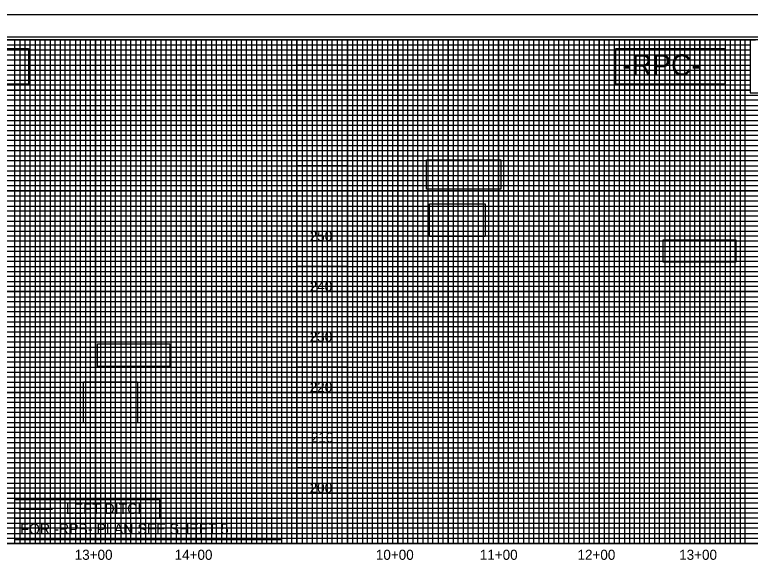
# Model space of a CAD drawing. Extents: x 1810963 to 1812960, y 722070 to 723170.
# Drawn here: x 1811500 to 1812230, y 722624 to 723170 of the extents above; entities that cross this region are included whole.
import ezdxf

# ---------------------------------------------------------------- set-up
doc = ezdxf.new("R2010")
doc.units = 0
for name, color, linetype in [('Exist Horizontal Alignment Tick Label', 7, 'Continuous'), ('Old_Level_11', 7, 'Continuous'), ('Old_Level_2', 7, 'Continuous'), ('Prop Conc 2ft 6in Curb and Gutter', 7, 'Continuous'), ('Prop RDY Traffic Signal CELL', 7, 'Continuous'), ('Prop Shade Heavy', 7, 'Continuous'), ('Prop Shade Light', 7, 'Continuous'), ('Prop Vertical Profile Ditch Grade Left', 7, 'Continuous'), ('Scratch_Level_3', 7, 'Continuous'), ('Sheet Block Title CELL', 7, 'Continuous'), ('Sheet Layout Profile Border Port 1', 7, 'Continuous'), ('Sheet North Arrow CELL', 7, 'Continuous'), ('Sheet Symbology CELL', 7, 'Continuous'), ('Sheet Title CELL', 7, 'Continuous')]:
    doc.layers.add(name, color=color, linetype=linetype)

msp = doc.modelspace()

# ---------------------------------------------------------------- linework, layer by layer
at = {"layer": 'Old_Level_11'}
msp.add_lwpolyline([(1810976.46, 722092.33), (1812642.96, 722092.33), (1812642.96, 723147.43), (1810976.46, 723147.43)], close=True, dxfattribs=at)
at = {"layer": 'Old_Level_2'}
for p, q in [((1811830.46, 723119.88), (1811780.46, 723119.88)), ((1811830.46, 723094.88), (1811780.46, 723094.88)), ((1811830.46, 723069.88), (1811780.46, 723069.88)), ((1811830.46, 723044.88), (1811780.46, 723044.88)), ((1811830.46, 723019.88), (1811780.46, 723019.88)), ((1811830.46, 722994.88), (1811780.46, 722994.88)), ((1811830.46, 722969.88), (1811780.46, 722969.88)), ((1811830.46, 722944.88), (1811780.46, 722944.88)), ((1811830.46, 722919.88), (1811780.46, 722919.88)), ((1811830.46, 722894.88), (1811780.46, 722894.88)), ((1811830.46, 722869.88), (1811780.46, 722869.88)), ((1811830.46, 722844.88), (1811780.46, 722844.88)), ((1811830.46, 722819.88), (1811780.46, 722819.88)), ((1811830.46, 722794.88), (1811780.46, 722794.88)), ((1811830.46, 722769.88), (1811780.46, 722769.88)), ((1811830.46, 722744.88), (1811780.46, 722744.88)), ((1811830.46, 722719.88), (1811780.46, 722719.88)), ((1811830.46, 722694.88), (1811780.46, 722694.88)), ((1811830.46, 722669.88), (1811780.46, 722669.88))]:
    msp.add_line(p, q, dxfattribs=at)
for points in [[(1811780.46, 723144.88), (1811830.46, 723144.88), (1811830.46, 722644.88), (1811780.46, 722644.88)], [(1811405.74, 723136.45), (1811513.83, 723136.45), (1811513.83, 723101.06), (1811405.74, 723101.06)], [(1812096.99, 723136.45), (1812205.08, 723136.45), (1812205.08, 723101.06), (1812096.99, 723101.06)], [(1811909.02, 723025.89), (1811982.71, 723025.89), (1811982.71, 722996.59), (1811909.02, 722996.59)], [(1811911.85, 722982.22), (1811967.42, 722982.22), (1811967.42, 722949.63), (1811911.85, 722949.63)], [(1812144.06, 722946.5), (1812215.98, 722946.5), (1812215.98, 722924.17), (1812144.06, 722924.17)], [(1811582.43, 722843.13), (1811654.35, 722843.13), (1811654.35, 722820.5), (1811582.43, 722820.5)], [(1811568.44, 722805.35), (1811622.21, 722805.35), (1811622.21, 722764.67), (1811568.44, 722764.67)], [(1811500.38, 722688.37), (1811644.05, 722688.37), (1811644.05, 722669.88), (1811500.38, 722669.88)], [(1811500.38, 722669.88), (1811765.06, 722669.88), (1811765.06, 722648.36), (1811500.38, 722648.36)]]:
    msp.add_lwpolyline(points, close=True, dxfattribs=at)
at = {"layer": 'Prop Conc 2ft 6in Curb and Gutter'}
for p, q in [((1811530.46, 722644.88), (1811530.46, 723144.88)), ((1811580.46, 722644.88), (1811580.46, 723144.88)), ((1811630.46, 722644.88), (1811630.46, 723144.88)), ((1811680.46, 722644.88), (1811680.46, 723144.88)), ((1811730.46, 722644.88), (1811730.46, 723144.88)), ((1811780.46, 722644.88), (1811780.46, 723144.88)), ((1811780.46, 722644.88), (1811780.46, 723144.88)), ((1811780.46, 723144.88), (1811780.46, 722644.88)), ((1811830.46, 722644.88), (1811830.46, 723144.88)), ((1811830.46, 722644.88), (1811830.46, 723144.88)), ((1811830.46, 723144.88), (1811830.46, 722644.88)), ((1811880.46, 722644.88), (1811880.46, 723144.88)), ((1811880.46, 723144.88), (1811880.46, 722644.88)), ((1811880.46, 723144.88), (1811880.46, 722644.88)), ((1811930.46, 722644.88), (1811930.46, 723144.88)), ((1811930.46, 723144.88), (1811930.46, 722644.88)), ((1811930.46, 723144.88), (1811930.46, 722644.88)), ((1811980.46, 722644.88), (1811980.46, 723144.88)), ((1812030.46, 722644.88), (1812030.46, 723144.88)), ((1812080.46, 722644.88), (1812080.46, 723144.88)), ((1812130.46, 722644.88), (1812130.46, 723144.88)), ((1812180.46, 722644.88), (1812180.46, 723144.88)), ((1812230.42, 723094.88), (1811130.46, 723094.88)), ((1812430.41, 723044.88), (1811130.46, 723044.88)), ((1812430.46, 722994.88), (1811130.46, 722994.88)), ((1812630.46, 722944.88), (1811130.46, 722944.88)), ((1812630.46, 722894.88), (1811130.46, 722894.88)), ((1812630.46, 722844.88), (1811130.46, 722844.88)), ((1812630.46, 722794.88), (1811130.46, 722794.88)), ((1812630.46, 722744.88), (1811130.46, 722744.88)), ((1812630.46, 722694.88), (1811130.46, 722694.88))]:
    msp.add_line(p, q, dxfattribs=at)
at = {"layer": 'Prop RDY Traffic Signal CELL'}
msp.add_line((1812647.46, 723169.88), (1810963.46, 723169.88), dxfattribs=at)
at = {"layer": 'Prop Shade Heavy'}
for p, q in [((1811780.46, 723144.88), (1811830.46, 723144.88)), ((1811880.46, 723144.88), (1811930.46, 723144.88))]:
    msp.add_line(p, q, dxfattribs=at)
for points in [[(1811480.46, 722644.88), (1811530.46, 722644.88), (1811530.46, 723144.88), (1811580.46, 723144.88), (1811580.46, 722644.88), (1811630.46, 722644.88), (1811630.46, 723144.88), (1811680.46, 723144.88), (1811680.46, 722644.88), (1811730.46, 722644.88), (1811730.46, 723144.88), (1811780.46, 723144.88), (1811780.46, 722644.88), (1811830.46, 722644.88), (1811830.46, 723144.88), (1811880.46, 723144.88), (1811880.46, 722644.88), (1811930.46, 722644.88), (1811930.46, 723144.88), (1811980.46, 723144.88), (1811980.46, 722644.88), (1812030.46, 722644.88), (1812030.46, 723144.88), (1812080.46, 723144.88), (1812080.46, 722644.88), (1812130.46, 722644.88), (1812130.46, 723144.88), (1812180.46, 723144.88), (1812180.46, 722644.88), (1812230.46, 722644.88)], [(1811130.46, 723094.88), (1812230.42, 723094.88)], [(1812430.46, 723044.88), (1811130.46, 723044.88), (1811130.46, 722994.88), (1812430.46, 722994.88)], [(1812630.46, 722944.88), (1811130.46, 722944.88), (1811130.46, 722894.88), (1812630.46, 722894.88)], [(1812630.46, 722844.88), (1811130.46, 722844.88), (1811130.46, 722794.88), (1812630.46, 722794.88)], [(1812630.46, 722744.88), (1811130.46, 722744.88), (1811130.46, 722744.88), (1811130.46, 722694.88), (1812630.46, 722694.88)]]:
    msp.add_lwpolyline(points, dxfattribs=at)
at = {"layer": 'Prop Shade Light'}
for p, q in [((1811455.46, 723144.88), (1811505.46, 723144.88)), ((1811505.46, 723144.88), (1811505.46, 722644.88)), ((1811555.46, 722644.88), (1811555.46, 723144.88)), ((1811555.46, 723144.88), (1811605.46, 723144.88)), ((1811605.46, 723144.88), (1811605.46, 722644.88)), ((1811655.46, 722644.88), (1811655.46, 723144.88)), ((1811655.46, 723144.88), (1811705.46, 723144.88)), ((1811705.46, 723144.88), (1811705.46, 722644.88)), ((1811755.46, 722644.88), (1811755.46, 723144.88)), ((1811755.46, 723144.88), (1811805.46, 723144.88)), ((1811805.46, 723144.88), (1811805.46, 722644.88)), ((1811855.46, 722644.88), (1811855.46, 723144.88)), ((1811855.46, 723144.88), (1811905.46, 723144.88)), ((1811905.46, 723144.88), (1811905.46, 722644.88)), ((1811955.46, 722644.88), (1811955.46, 723144.88)), ((1811955.46, 723144.88), (1812005.46, 723144.88)), ((1812005.46, 723144.88), (1812005.46, 722644.88)), ((1812055.46, 722644.88), (1812055.46, 723144.88)), ((1812055.46, 723144.88), (1812105.46, 723144.88)), ((1812105.46, 723144.88), (1812105.46, 722644.88)), ((1812155.46, 722644.88), (1812155.46, 723144.88)), ((1812155.46, 723144.88), (1812205.46, 723144.88)), ((1812205.46, 723144.88), (1812205.46, 722644.88)), ((1811130.46, 723119.88), (1812230.42, 723119.88)), ((1811505.46, 722644.88), (1811555.46, 722644.88)), ((1811605.46, 722644.88), (1811655.46, 722644.88)), ((1811705.46, 722644.88), (1811755.46, 722644.88)), ((1811755.46, 722644.88), (1811755.46, 722644.88)), ((1811805.46, 722644.88), (1811855.46, 722644.88)), ((1811905.46, 722644.88), (1811955.46, 722644.88)), ((1812005.46, 722644.88), (1812055.46, 722644.88)), ((1812105.46, 722644.88), (1812155.46, 722644.88)), ((1812205.46, 722644.88), (1812255.46, 722644.88))]:
    msp.add_line(p, q, dxfattribs=at)
for points in [[(1812430.46, 723069.88), (1811130.46, 723069.88), (1811130.46, 723019.88), (1812430.46, 723019.88)], [(1812630.46, 722969.88), (1811130.46, 722969.88), (1811130.46, 722919.88), (1812455.46, 722919.88)], [(1812630.46, 722869.88), (1811130.46, 722869.88), (1811130.46, 722819.88), (1812630.46, 722819.88)], [(1812630.46, 722769.88), (1811130.46, 722769.88), (1811130.46, 722719.88), (1812630.46, 722719.88)], [(1812630.46, 722669.88), (1811130.46, 722669.88)]]:
    msp.add_lwpolyline(points, dxfattribs=at)
at = {"layer": 'Prop Vertical Profile Ditch Grade Left'}
msp.add_line((1811504.29, 722679.06), (1811537.94, 722679.06), dxfattribs=at)
at = {"layer": 'Scratch_Level_3'}
msp.add_lwpolyline([(1811180.46, 723144.88), (1812230.46, 723144.88), (1812230.46, 723092.45), (1812430.5, 723092.45), (1812430.41, 722983.83), (1812580.46, 722983.83), (1812580.46, 722644.88), (1811180.46, 722644.88)], close=True, dxfattribs=at)
at = {"layer": 'Sheet Layout Profile Border Port 1'}
msp.add_lwpolyline([(1811180.46, 722983.83), (1811180.46, 722644.88), (1812580.46, 722644.88), (1812580.46, 722983.83)], dxfattribs=at)
at = {"layer": 'Sheet North Arrow CELL'}
msp.add_lwpolyline([(1810963.46, 722069.88), (1812647.46, 722069.88), (1812647.46, 723169.88), (1810963.46, 723169.88)], close=True, dxfattribs=at)
at = {"layer": 'Sheet Symbology CELL'}
msp.add_line((1811130.46, 722644.88), (1812630.46, 722644.88), dxfattribs=at)
msp.add_lwpolyline([(1812630.46, 723144.88), (1811130.46, 723144.88), (1811130.46, 722094.88), (1812630.46, 722094.88)], close=True, dxfattribs=at)
at = {"layer": 'Sheet Title CELL'}
for p, q in [((1811180.46, 723139.88), (1812230.42, 723139.88)), ((1812015.46, 722644.88), (1812015.46, 723144.88)), ((1812015.46, 723144.88), (1812020.46, 723144.88)), ((1812020.46, 723144.88), (1812020.46, 722644.88)), ((1812025.46, 722644.88), (1812025.46, 723144.88)), ((1812025.46, 723144.88), (1812035.46, 723144.88)), ((1812035.46, 723144.88), (1812035.46, 722644.88)), ((1812040.46, 722644.88), (1812040.46, 723144.88)), ((1812040.46, 723144.88), (1812045.46, 723144.88)), ((1812045.46, 723144.88), (1812045.46, 722644.88)), ((1812050.46, 722644.88), (1812050.46, 723144.88)), ((1812050.46, 723144.88), (1812060.46, 723144.88)), ((1812060.46, 723144.88), (1812060.46, 722644.88)), ((1812065.46, 722644.88), (1812065.46, 723144.88)), ((1812065.46, 723144.88), (1812070.46, 723144.88)), ((1812070.46, 723144.88), (1812070.46, 722644.88)), ((1812075.46, 722644.88), (1812075.46, 723144.88)), ((1812075.46, 723144.88), (1812085.46, 723144.88)), ((1812085.46, 723144.88), (1812085.46, 722644.88)), ((1812090.46, 722644.88), (1812090.46, 723144.88)), ((1812090.46, 723144.88), (1812095.46, 723144.88)), ((1812095.46, 723144.88), (1812095.46, 722644.88)), ((1812100.46, 722644.88), (1812100.46, 723144.88)), ((1812100.46, 723144.88), (1812110.46, 723144.88)), ((1812110.46, 723144.88), (1812110.46, 722644.88)), ((1812115.46, 722644.88), (1812115.46, 723144.88)), ((1812115.46, 723144.88), (1812120.46, 723144.88)), ((1812120.46, 723144.88), (1812120.46, 722644.88)), ((1812125.46, 722644.88), (1812125.46, 723144.88)), ((1812125.46, 723144.88), (1812135.46, 723144.88)), ((1812135.46, 723144.88), (1812135.46, 722644.88)), ((1812140.46, 722644.88), (1812140.46, 723144.88)), ((1812140.46, 723144.88), (1812145.46, 723144.88)), ((1812145.46, 723144.88), (1812145.46, 722644.88)), ((1812150.46, 722644.88), (1812150.46, 723144.88)), ((1812150.46, 723144.88), (1812160.46, 723144.88)), ((1812160.46, 723144.88), (1812160.46, 722644.88)), ((1812165.46, 722644.88), (1812165.46, 723144.88)), ((1812165.46, 723144.88), (1812170.46, 723144.88)), ((1812170.46, 723144.88), (1812170.46, 722644.88)), ((1812175.46, 722644.88), (1812175.46, 723144.88)), ((1812175.46, 723144.88), (1812185.46, 723144.88)), ((1812185.46, 723144.88), (1812185.46, 722644.88)), ((1812190.46, 722644.88), (1812190.46, 723144.88)), ((1812190.46, 723144.88), (1812195.46, 723144.88)), ((1812195.46, 723144.88), (1812195.46, 722644.88)), ((1812200.46, 722644.88), (1812200.46, 723144.88)), ((1812200.46, 723144.88), (1812210.46, 723144.88)), ((1812210.46, 723144.88), (1812210.46, 722644.88)), ((1812215.46, 722644.88), (1812215.46, 723144.88)), ((1812215.46, 723144.88), (1812220.46, 723144.88)), ((1812220.46, 723144.88), (1812220.46, 722644.88)), ((1812225.46, 722644.88), (1812225.46, 723144.88)), ((1812225.46, 723144.88), (1812235.46, 723144.88)), ((1812230.42, 723134.82), (1811180.46, 723134.53)), ((1811180.46, 723129.88), (1812230.42, 723129.88)), ((1812230.42, 723099.88), (1811180.46, 723099.88)), ((1811180.46, 723089.88), (1812430.46, 723089.88)), ((1812430.41, 723009.88), (1811180.46, 723009.88)), ((1812430.46, 723004.88), (1811180.46, 723004.88)), ((1812430.46, 722999.88), (1811180.46, 722999.88)), ((1811180.46, 722989.88), (1812430.46, 722989.88)), ((1812430.46, 722984.88), (1811180.46, 722984.88)), ((1811180.46, 722979.88), (1812580.46, 722979.88)), ((1812580.46, 722959.88), (1811180.46, 722959.88)), ((1811180.46, 722954.88), (1812580.46, 722954.88)), ((1812580.46, 722934.88), (1811180.46, 722934.88)), ((1811180.46, 722929.88), (1812580.46, 722929.88)), ((1812580.46, 722909.88), (1811180.46, 722909.88)), ((1811180.46, 722904.88), (1812580.46, 722904.88)), ((1812580.46, 722899.88), (1811180.46, 722899.88)), ((1811180.46, 722889.88), (1812580.46, 722889.88)), ((1812580.46, 722884.88), (1811180.46, 722884.88)), ((1811180.46, 722879.88), (1812580.46, 722879.88)), ((1812580.46, 722874.88), (1811180.46, 722874.88)), ((1811180.46, 722864.88), (1812580.46, 722864.88)), ((1812580.46, 722859.88), (1811180.46, 722859.88)), ((1811180.46, 722854.88), (1812580.46, 722854.88)), ((1812580.46, 722849.88), (1811180.46, 722849.88)), ((1811180.46, 722839.88), (1812580.46, 722839.88)), ((1812580.46, 722834.88), (1811180.46, 722834.88)), ((1811180.46, 722829.88), (1812580.46, 722829.88)), ((1812580.46, 722824.88), (1811180.46, 722824.88)), ((1811180.46, 722814.88), (1812580.46, 722814.88)), ((1812580.46, 722809.88), (1811180.46, 722809.88)), ((1811180.46, 722804.88), (1812580.46, 722804.88)), ((1812580.46, 722799.88), (1811180.46, 722799.88)), ((1811180.46, 722789.88), (1812580.46, 722789.88)), ((1812580.46, 722784.88), (1811180.46, 722784.88)), ((1811180.46, 722779.88), (1812580.46, 722779.88)), ((1812580.46, 722774.88), (1811180.46, 722774.88)), ((1811180.46, 722764.88), (1812580.46, 722764.88)), ((1812580.46, 722759.88), (1811180.46, 722759.88)), ((1812580.46, 722754.88), (1811180.46, 722754.88)), ((1812580.46, 722749.88), (1811180.46, 722749.88)), ((1811180.46, 722739.88), (1812580.46, 722739.88)), ((1812580.46, 722734.88), (1811180.46, 722734.88)), ((1811180.46, 722729.88), (1812580.46, 722729.88)), ((1812580.46, 722724.88), (1811180.46, 722724.88)), ((1811180.46, 722714.88), (1812580.46, 722714.88)), ((1812580.46, 722709.88), (1811180.46, 722709.88)), ((1811180.46, 722704.88), (1812580.46, 722704.88)), ((1812580.46, 722699.88), (1811180.46, 722699.88)), ((1811180.46, 722689.88), (1812580.46, 722689.88)), ((1812580.46, 722684.88), (1811180.46, 722684.88)), ((1811180.46, 722679.88), (1812580.46, 722679.88)), ((1812580.46, 722674.88), (1811180.46, 722674.88)), ((1811180.46, 722664.88), (1812580.46, 722664.88)), ((1812580.46, 722659.88), (1811180.46, 722659.88)), ((1811180.46, 722654.88), (1812580.46, 722654.88)), ((1812020.46, 722644.88), (1812025.46, 722644.88)), ((1812035.46, 722644.88), (1812040.46, 722644.88)), ((1812045.46, 722644.88), (1812050.46, 722644.88)), ((1812060.46, 722644.88), (1812065.46, 722644.88)), ((1812070.46, 722644.88), (1812075.46, 722644.88)), ((1812085.46, 722644.88), (1812090.46, 722644.88)), ((1812095.46, 722644.88), (1812100.46, 722644.88)), ((1812110.46, 722644.88), (1812115.46, 722644.88)), ((1812120.46, 722644.88), (1812125.46, 722644.88)), ((1812135.46, 722644.88), (1812140.46, 722644.88)), ((1812145.46, 722644.88), (1812150.46, 722644.88)), ((1812160.46, 722644.88), (1812165.46, 722644.88)), ((1812170.46, 722644.88), (1812175.46, 722644.88)), ((1812185.46, 722644.88), (1812190.46, 722644.88)), ((1812195.46, 722644.88), (1812200.46, 722644.88)), ((1812210.46, 722644.88), (1812215.46, 722644.88)), ((1812220.46, 722644.88), (1812225.46, 722644.88))]:
    msp.add_line(p, q, dxfattribs=at)
for points in [[(1811495.46, 722644.88), (1811500.46, 722644.88), (1811500.46, 723144.88), (1811510.46, 723144.88), (1811510.46, 722644.88), (1811515.46, 722644.88), (1811515.46, 723144.88), (1811520.46, 723144.88), (1811520.46, 722644.88), (1811525.46, 722644.88), (1811525.46, 723144.88), (1811535.46, 723144.88), (1811535.46, 722644.88), (1811540.46, 722644.88), (1811540.46, 723144.88), (1811545.46, 723144.88), (1811545.46, 722644.88), (1811550.46, 722644.88), (1811550.46, 723144.88), (1811560.46, 723144.88), (1811560.46, 722644.88), (1811565.46, 722644.88), (1811565.46, 723144.88), (1811570.46, 723144.88), (1811570.46, 722644.88), (1811575.46, 722644.88), (1811575.46, 723144.88), (1811585.46, 723144.88), (1811585.46, 722644.88), (1811590.46, 722644.88), (1811590.46, 723144.88), (1811595.46, 723144.88), (1811595.46, 722644.88), (1811600.46, 722644.88), (1811600.46, 723144.88), (1811610.46, 723144.88), (1811610.46, 722644.88), (1811615.46, 722644.88), (1811615.46, 723144.88), (1811620.46, 723144.88), (1811620.46, 722644.88), (1811625.46, 722644.88), (1811625.46, 723144.88), (1811635.46, 723144.88), (1811635.46, 722644.88), (1811640.46, 722644.88), (1811640.46, 723144.88), (1811645.46, 723144.88), (1811645.46, 722644.88), (1811650.46, 722644.88), (1811650.46, 723144.88), (1811660.46, 723144.88), (1811660.46, 722644.88), (1811665.46, 722644.88), (1811665.46, 723144.88), (1811670.46, 723144.88), (1811670.46, 722644.88), (1811675.46, 722644.88), (1811675.46, 723144.88), (1811685.46, 723144.88), (1811685.46, 722644.88), (1811690.46, 722644.88), (1811690.46, 723144.88), (1811695.46, 723144.88), (1811695.46, 722644.88), (1811700.46, 722644.88), (1811700.46, 723144.88), (1811710.46, 723144.88)], [(1811710.46, 723144.88), (1811710.46, 722644.88), (1811715.46, 722644.88), (1811715.46, 723144.88), (1811720.46, 723144.88), (1811720.46, 722644.88), (1811725.46, 722644.88), (1811725.46, 723144.88), (1811735.46, 723144.88), (1811735.46, 722644.88), (1811740.46, 722644.88), (1811740.46, 723144.88), (1811745.46, 723144.88), (1811745.46, 722644.88), (1811750.46, 722644.88), (1811750.46, 723144.88), (1811760.46, 723144.88), (1811760.46, 722644.88), (1811765.46, 722644.88), (1811765.46, 723144.88), (1811770.46, 723144.88), (1811770.46, 722644.88), (1811775.46, 722644.88), (1811775.46, 723144.88), (1811785.46, 723144.88), (1811785.46, 722644.88), (1811790.46, 722644.88), (1811790.46, 723144.88), (1811795.46, 723144.88), (1811795.46, 722644.88), (1811800.46, 722644.88), (1811800.46, 723144.88), (1811810.46, 723144.88), (1811810.46, 722644.88), (1811815.46, 722644.88), (1811815.46, 723144.88), (1811820.46, 723144.88), (1811820.46, 722644.88), (1811825.46, 722644.88), (1811825.46, 723144.88), (1811835.46, 723144.88), (1811835.46, 722644.88), (1811835.46, 722644.88), (1811840.46, 722644.88), (1811840.46, 723144.88), (1811845.46, 723144.88), (1811845.46, 722644.88), (1811850.46, 722644.88), (1811850.46, 723144.88), (1811860.46, 723144.88), (1811860.46, 722644.88), (1811865.46, 722644.88), (1811865.46, 723144.88), (1811870.46, 723144.88), (1811870.46, 722644.88), (1811875.46, 722644.88), (1811875.46, 723144.88), (1811885.46, 723144.88), (1811885.46, 722644.88), (1811890.46, 722644.88), (1811890.46, 723144.88), (1811895.46, 723144.88), (1811895.46, 722644.88), (1811900.46, 722644.88), (1811900.46, 723144.88), (1811910.46, 723144.88), (1811910.46, 722644.88), (1811915.46, 722644.88), (1811915.46, 723144.88), (1811920.46, 723144.88), (1811920.46, 722644.88), (1811925.46, 722644.88), (1811925.46, 723144.88), (1811935.46, 723144.88), (1811935.46, 722644.88), (1811940.46, 722644.88), (1811940.46, 723144.88), (1811945.46, 723144.88), (1811945.46, 722644.88), (1811950.46, 722644.88), (1811950.46, 723144.88), (1811960.46, 723144.88), (1811960.46, 722644.88), (1811965.46, 722644.88), (1811965.46, 723144.88), (1811970.46, 723144.88), (1811970.46, 722644.88), (1811975.46, 722644.88), (1811975.46, 723144.88), (1811985.46, 723144.88), (1811985.46, 722644.88), (1811990.16, 722645.43), (1811990.46, 722644.88), (1811990.46, 723144.88), (1811995.46, 723144.88), (1811995.46, 722644.88), (1812000.46, 722644.88), (1812000.46, 723144.88), (1812010.46, 723144.88), (1812010.46, 722644.88), (1812015.46, 722644.88)], [(1812230.42, 723124.88), (1811180.46, 723124.88), (1811180.46, 723114.88), (1812230.42, 723114.88)], [(1812230.42, 723109.88), (1811180.46, 723109.88), (1811180.46, 723104.88), (1812230.42, 723104.88)], [(1812430.46, 723084.88), (1811180.46, 723084.88), (1811180.46, 723079.88), (1812430.46, 723079.88)], [(1812430.46, 723074.88), (1811180.46, 723074.88), (1811180.46, 723064.88), (1812430.46, 723064.88)], [(1812430.46, 723059.88), (1811180.46, 723059.88), (1811180.46, 723054.88), (1812430.46, 723054.88)], [(1812430.46, 723049.88), (1811180.46, 723049.88), (1811180.46, 723039.88), (1812430.46, 723039.88)], [(1812430.46, 723034.78), (1811180.56, 723034.78), (1811180.56, 723029.88), (1812430.46, 723029.88)], [(1812430.46, 723024.88), (1811180.46, 723024.88), (1811180.46, 723014.88), (1812430.46, 723014.88)], [(1812580.46, 722974.88), (1811180.46, 722974.88), (1811180.46, 722964.88), (1812580.46, 722964.88)], [(1812580.46, 722949.88), (1811180.46, 722949.88), (1811180.46, 722939.88), (1812580.46, 722939.88)], [(1812580.46, 722924.88), (1811180.46, 722924.88), (1811180.46, 722914.88), (1812580.46, 722914.88)], [(1812580.46, 722649.88), (1811180.46, 722649.88)]]:
    msp.add_lwpolyline(points, dxfattribs=at)

# ---------------------------------------------------------------- texts
at = {"layer": 'Exist Horizontal Alignment Tick Label'}
for s, height, p in [('-RPC-', 21, (1812103.39, 723109.49)), ('LEFT DITCH', 10.5, (1811551.11, 722674.13)), ('FOR -RPB- PLAN SEE SHEET 5', 10.5, (1811505.86, 722654.07))]:
    msp.add_text(s, height=height, rotation=360, dxfattribs=at).set_placement(p)
at = {"layer": 'Old_Level_2'}
for s, p in [('250', (1811793.1, 722945.13)), ('240', (1811793.1, 722895.13)), ('230', (1811793.1, 722845.13)), ('220', (1811793.1, 722795.13)), ('210', (1811794.29, 722745.13)), ('200', (1811793.1, 722695.13))]:
    msp.add_text(s, height=10, dxfattribs=at).set_placement(p)
at = {"layer": 'Sheet Block Title CELL'}
for s, p in [('13+00', (1811559.84, 722628.6)), ('14+00', (1811659.01, 722628.6)), ('10+00', (1811858.78, 722628.6)), ('11+00', (1811961.94, 722628.6)), ('12+00', (1812058.92, 722628.6)), ('13+00', (1812159.84, 722628.6))]:
    msp.add_text(s, height=10, dxfattribs=at).set_placement(p)

doc.saveas('drawing.dxf')
